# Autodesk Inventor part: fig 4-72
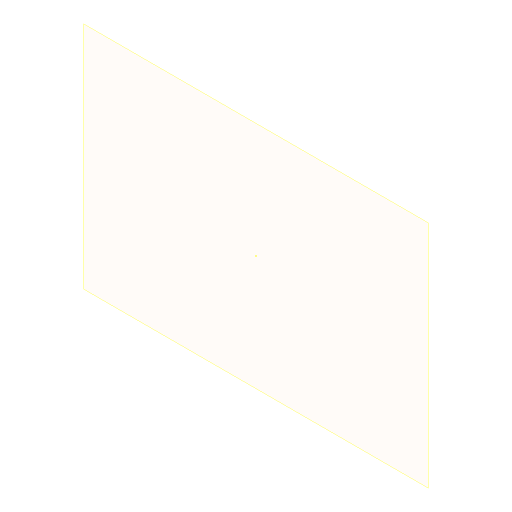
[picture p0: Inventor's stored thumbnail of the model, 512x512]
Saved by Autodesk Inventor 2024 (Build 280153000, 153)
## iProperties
Created: 2015-07
Part Number: fig 4-72
Material: Generic
Document SubType Name: Modeling
Designer: Sandeep
Density: 1 g/cm^3
Appearance: Default
Author: Sandeep
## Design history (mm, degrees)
feature "Form1"
sketch "Sketch1"
  geometry: 1 further point
  constraints: 1 other
body "Srf1"
